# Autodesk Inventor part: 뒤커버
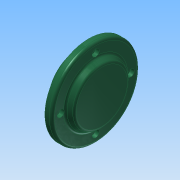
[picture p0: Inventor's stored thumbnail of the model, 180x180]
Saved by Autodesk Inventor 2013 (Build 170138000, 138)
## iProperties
Created: 2015-11
Part Number: 뒤커버
Material: 알루미늄 6061
Document SubType Name: Modeling
Designer: mduedu
Density: 2.71 g/cm^3
Mass: 309.118 g
Surface Area: 231.217 cm^2
Volume: 114.066 cm^3
Author: mduedu
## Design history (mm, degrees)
sketch "스케치1"
  geometry: C1 r 50 at (0, 0); 1 further point
  constraints: 1 centre point, 1 coincident
  dimensions: "d42" = 100 diameter of C1
extrude "돌출1" new body sketch "스케치1" distance "d3" = 8; taper "d4" = 0 deg
sketch "스케치2"
  geometry: C1 r 35 at (0, 0); 1 further point
  constraints: 1 centre point, 1 coincident
  dimensions: "d5" = 70 diameter of C1
extrude "돌출2" join sketch "스케치2" distance "d6" = 7; taper "d7" = -30 deg
sketch "스케치5" dims "d44" = 80
  geometry: 3 further points
  constraints: 2 vertical alignment, 1 coincident, 2 other
hole "구멍3" sketch "스케치5" at (0, 40) diameter "d45" = 4.5; stored, may be unused: countersink angle "d49" = 90 deg, drill point angle "d51" = 118 deg; dims "d46" = 6, "d47" = 8, "d48" = 4.4, "d50" = 8
sketch "스케치4"
  geometry: C1 r 35 at (0, 0); 1 further point
  constraints: 1 centre point, 1 coincident
  dimensions: "d21" = 70 diameter of C1
extrude "돌출3" join sketch "스케치4" distance "d23" = 12; taper "d24" = 0 deg
hole "구멍2" diameter "d27" = 30; stored, may be unused: countersink angle "d31" = 90 deg, drill point angle "d33" = 0 deg; dims "d25" = 10, "d26" = 10, "d28" = 6, "d29" = 40, "d30" = 12, "d32" = 15
fillet "모깎기3" dims "d36" = 3
fillet "모깎기4" dims "d37" = 3
fillet "모깎기5" dims "d38" = 0.3
chamfer "모따기1" distance "d39" = 1; stored, may be unused: second distance "d40" = 2, angle "d41" = 45 deg
node "솔리드1"
pattern_circular "원형 패턴2" dims angle "d53" = 360 deg
